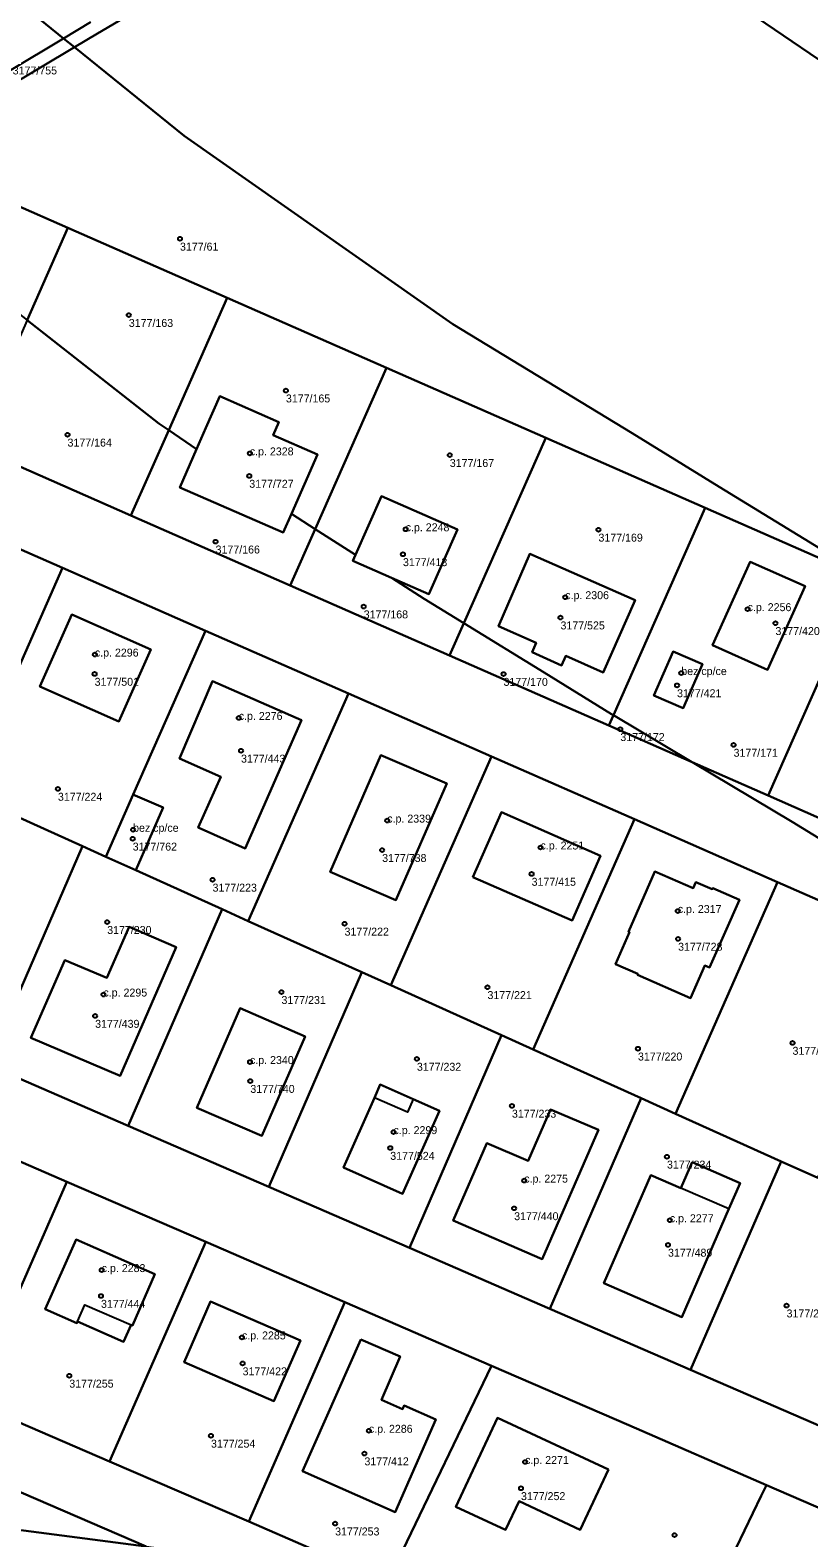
# Model space of a CAD drawing. Extents: x -878211 to -870363, y -1058464 to -1052522.
# Drawn here: x -874243.4 to -874145.4, y -1057039.9 to -1056850 of the extents above; entities that cross this region are included whole.
import ezdxf

# ---------------------------------------------------------------- set-up
doc = ezdxf.new("R2010")
doc.units = 0
for name, color, linetype in [('Definiční body', 7, 'Continuous'), ('Polygon budovy', 7, 'Continuous'), ('Polygon parcely', 7, 'Continuous')]:
    doc.layers.add(name, color=color, linetype=linetype)

msp = doc.modelspace()

# ---------------------------------------------------------------- linework, layer by layer
at = {"layer": 'Definiční body'}
for centre in [(-874224.5, -1056876.24994), (-874230.94, -1056885.85994), (-874211.17, -1056895.36994), (-874238.65, -1056900.92994), (-874215.71, -1056903.27994), (-874190.55, -1056903.49994), (-874215.78, -1056906.11994), (-874196.1, -1056912.83994), (-874171.84, -1056912.89994), (-874220.02, -1056914.39994), (-874196.44, -1056915.98994), (-874176.02, -1056921.38994), (-874201.38, -1056922.56994), (-874153.07, -1056922.89994), (-874176.62, -1056923.95994), (-874149.57, -1056924.66994), (-874235.21, -1056928.61994), (-874235.24, -1056931.05994), (-874183.79, -1056931.06994), (-874161.42, -1056930.94994), (-874161.95, -1056932.49994), (-874217.1, -1056936.59994), (-874169.09, -1056938.01994), (-874216.82, -1056940.73994), (-874154.84, -1056939.99994), (-874239.86, -1056945.53994), (-874198.42, -1056949.52994), (-874230.45, -1056951.81994), (-874230.4, -1056950.68994), (-874199.06, -1056953.24994), (-874179.13, -1056952.91994), (-874220.4, -1056956.98994), (-874180.25, -1056956.24994), (-874161.86, -1056960.91994), (-874233.66, -1056962.31994), (-874203.79, -1056962.52994), (-874161.82, -1056964.42994), (-874211.73, -1056971.13994), (-874185.81, -1056970.51994), (-874234.13, -1056971.43994), (-874235.18, -1056974.13994), (-874166.87, -1056978.25994), (-874147.42, -1056977.53994), (-874215.69, -1056979.93994), (-874194.69, -1056979.54994), (-874215.65, -1056982.33994), (-874182.73, -1056985.45994), (-874197.63, -1056988.76994), (-874198.04, -1056990.76994), (-874163.22, -1056991.86994), (-874181.18, -1056994.87994), (-874182.45, -1056998.36994), (-874162.86, -1056999.86994), (-874163.09, -1057002.96994), (-874234.35, -1057006.14994), (-874234.44, -1057009.40994), (-874148.17, -1057010.61994), (-874216.7, -1057014.62994), (-874216.62, -1057017.90994), (-874238.43, -1057019.45994), (-874220.6, -1057027.01994), (-874200.73, -1057026.38994), (-874201.29, -1057029.24994), (-874181.07, -1057030.31994), (-874181.59, -1057033.62994), (-874204.98, -1057038.07994), (-874162.27, -1057039.52994)]:
    msp.add_circle(centre, 0.25, dxfattribs=at)
at = {"layer": 'Polygon budovy'}
for points in [[(-874210.47, -1056910.89), (-874207.19, -1056903.42), (-874212.78, -1056901), (-874212.05, -1056899.36), (-874219.5, -1056896.09), (-874221.25, -1056900.07), (-874222.42, -1056902.76), (-874224.52, -1056907.56), (-874211.51, -1056913.25)], [(-874202.4, -1056916.07), (-874202.73, -1056916.83), (-874197.89, -1056918.96), (-874193.18, -1056921.03), (-874189.59, -1056912.87), (-874199.13, -1056908.66)], [(-874176.49, -1056929.98), (-874175.96, -1056928.77), (-874171.23, -1056930.86), (-874167.22, -1056921.75), (-874180.46, -1056915.95), (-874184.44, -1056925.03), (-874179.68, -1056927.13), (-874180.2, -1056928.32)], [(-874152.76, -1056916.92), (-874157.49, -1056927.45), (-874150.57, -1056930.55), (-874145.82, -1056919.99)], [(-874228.18, -1056927.97), (-874238.13, -1056923.59), (-874242.13, -1056932.65), (-874232.18, -1056937.03)], [(-874162.45, -1056928.24), (-874164.89, -1056933.76), (-874161.18, -1056935.39), (-874158.74, -1056929.81)], [(-874224.55, -1056941.7), (-874219.38, -1056944.03), (-874222.2, -1056950.41), (-874216.3, -1056953.03), (-874209.22, -1056936.87), (-874220.4, -1056931.97)], [(-874205.6, -1056955.97), (-874197.33, -1056959.57), (-874190.94, -1056944.87), (-874199.21, -1056941.28)], [(-874230.38, -1056946.25), (-874233.82, -1056954.08), (-874230.04, -1056955.79), (-874226.61, -1056947.87), (-874230.14, -1056946.36)], [(-874187.63, -1056956.65), (-874175.14, -1056962.1), (-874171.57, -1056953.95), (-874184.06, -1056948.47)], [(-874167.94, -1056963.59), (-874169.7, -1056967.6), (-874166.88, -1056968.82), (-874166.94, -1056968.96), (-874160.27, -1056971.88), (-874158.45, -1056967.78), (-874157.85, -1056968.04), (-874154.08, -1056959.52), (-874157.46, -1056958.05), (-874157.53, -1056958.18), (-874159.57, -1056957.28), (-874159.92, -1056958.05), (-874164.73, -1056955.94), (-874168.08, -1056963.53)], [(-874243.26, -1056976.9), (-874232.01, -1056981.68), (-874224.97, -1056965.47), (-874230.9, -1056962.91), (-874233.72, -1056969.32), (-874238.98, -1056967.11)], [(-874222.37, -1056985.71), (-874214.19, -1056989.24), (-874208.76, -1056976.71), (-874216.94, -1056973.16)], [(-874200.03, -1056984.43), (-874203.91, -1056993.21), (-874196.5, -1056996.53), (-874191.84, -1056986.1), (-874195.16, -1056984.62), (-874195.89, -1056986.26)], [(-874190.14, -1056999.9), (-874178.91, -1057004.78), (-874171.83, -1056988.47), (-874177.86, -1056985.9), (-874180.69, -1056992.4), (-874185.9, -1056990.16)], [(-874165.25, -1056994.18), (-874171.17, -1057007.81), (-874161.34, -1057012.07), (-874155.42, -1056998.44), (-874161.48, -1056995.81)], [(-874237.56, -1057002.29), (-874241.47, -1057011.07), (-874237.48, -1057012.82), (-874237.4, -1057012.64), (-874236.47, -1057010.53), (-874230.66, -1057013.05), (-874230.48, -1057013.13), (-874227.66, -1057006.66)], [(-874220.68, -1057010.11), (-874223.97, -1057017.73), (-874212.7, -1057022.64), (-874209.33, -1057015.01)], [(-874201.76, -1057014.87), (-874209.09, -1057031.49), (-874197.42, -1057036.64), (-874192.29, -1057024.96), (-874196.31, -1057023.19), (-874196.52, -1057023.66), (-874199.16, -1057022.5), (-874196.78, -1057017.05)], [(-874170.59, -1057031.27), (-874184.53, -1057024.75), (-874189.77, -1057035.97), (-874183.54, -1057038.86), (-874181.82, -1057035.24), (-874174.14, -1057038.85)]]:
    msp.add_lwpolyline(points, close=True, dxfattribs=at)
at = {"layer": 'Polygon parcely'}
for points in [[(-874049.34, -1056914.15), (-874014.23, -1056932.75), (-874007.51, -1056921.23), (-874042.84, -1056899.69), (-874076.67, -1056880.17), (-874135.18, -1056846.79), (-874225.05, -1056794.29), (-874220.11, -1056799.06), (-874203.06, -1056813.57), (-874129.69, -1056863.48), (-874108.33, -1056874.46), (-874102.53, -1056878.64), (-874078.93, -1056895.35), (-874073.45, -1056899.05), (-874056.93, -1056909.47)], [(-874259.1, -1056860.81), (-874259.81, -1056863.37), (-874239.16, -1056851.02), (-874244.49, -1056846.71), (-874246.96, -1056851.65), (-874252.81, -1056857.48)], [(-874239.16, -1056851.02), (-874259.81, -1056863.37), (-874260.34, -1056865.3), (-874260.44, -1056865.68), (-874260.04, -1056865.43), (-874237.79, -1056852.13)], [(-874258.65, -1056866.05), (-874238.61, -1056874.87), (-874218.56, -1056883.68), (-874198.51, -1056892.5), (-874178.47, -1056901.32), (-874158.42, -1056910.14), (-874138.38, -1056918.96), (-874136.75, -1056919.68), (-874156.66, -1056907.49), (-874167.58, -1056900.75), (-874190.16, -1056887.02), (-874223.99, -1056863.27), (-874237.79, -1056852.13), (-874260.04, -1056865.43)], [(-874261.52, -1056872.54), (-874243.74, -1056886.5), (-874238.61, -1056874.87), (-874258.65, -1056866.05)], [(-874225.92, -1056900.36), (-874218.56, -1056883.68), (-874238.61, -1056874.87), (-874243.74, -1056886.5), (-874227.17, -1056899.5)], [(-874212.78, -1056901), (-874207.19, -1056903.42), (-874210.47, -1056910.89), (-874207.48, -1056912.81), (-874198.51, -1056892.5), (-874218.56, -1056883.68), (-874225.92, -1056900.36), (-874222.42, -1056902.76), (-874221.25, -1056900.07), (-874219.5, -1056896.09), (-874212.05, -1056899.36)], [(-874230.67, -1056911.11), (-874225.92, -1056900.36), (-874227.17, -1056899.5), (-874243.74, -1056886.5), (-874250.71, -1056902.29)], [(-874197.89, -1056918.96), (-874193.77, -1056921.6), (-874188.78, -1056924.67), (-874178.47, -1056901.32), (-874198.51, -1056892.5), (-874207.48, -1056912.81), (-874202.4, -1056916.07), (-874199.13, -1056908.66), (-874189.59, -1056912.87), (-874193.18, -1056921.03)], [(-874210.47, -1056910.89), (-874207.19, -1056903.42), (-874212.78, -1056901), (-874212.05, -1056899.36), (-874219.5, -1056896.09), (-874221.25, -1056900.07), (-874222.42, -1056902.76), (-874224.52, -1056907.56), (-874211.51, -1056913.25)], [(-874222.42, -1056902.76), (-874225.92, -1056900.36), (-874230.67, -1056911.11), (-874210.62, -1056919.93), (-874207.48, -1056912.81), (-874210.47, -1056910.89), (-874211.51, -1056913.25), (-874224.52, -1056907.56)], [(-874158.42, -1056910.14), (-874178.47, -1056901.32), (-874188.78, -1056924.67), (-874178.68, -1056930.87), (-874170.2, -1056936.13), (-874169.96, -1056936.27)], [(-874254.36, -1056944.8), (-874251.74, -1056945.99), (-874239.29, -1056917.7), (-874257.28, -1056909.78), (-874269.65, -1056937.89)], [(-874197.89, -1056918.96), (-874193.18, -1056921.03), (-874189.59, -1056912.87), (-874199.13, -1056908.66), (-874202.4, -1056916.07), (-874202.73, -1056916.83)], [(-874160.03, -1056942.19), (-874150.49, -1056946.39), (-874138.38, -1056918.96), (-874158.42, -1056910.14), (-874169.96, -1056936.27)], [(-874202.73, -1056916.83), (-874202.4, -1056916.07), (-874207.48, -1056912.81), (-874210.62, -1056919.93), (-874190.58, -1056928.75), (-874188.78, -1056924.67), (-874193.77, -1056921.6), (-874197.89, -1056918.96)], [(-874233.82, -1056954.08), (-874230.38, -1056946.25), (-874221.3, -1056925.63), (-874239.29, -1056917.7), (-874251.74, -1056945.99), (-874236.77, -1056952.75)], [(-874184.44, -1056925.03), (-874179.68, -1056927.13), (-874180.2, -1056928.32), (-874176.49, -1056929.98), (-874175.96, -1056928.77), (-874171.23, -1056930.86), (-874167.22, -1056921.75), (-874180.46, -1056915.95)], [(-874184.44, -1056925.03), (-874180.46, -1056915.95), (-874167.22, -1056921.75), (-874171.23, -1056930.86), (-874175.96, -1056928.77), (-874176.49, -1056929.98), (-874180.2, -1056928.32), (-874179.68, -1056927.13)], [(-874157.49, -1056927.45), (-874152.76, -1056916.92), (-874145.82, -1056919.99), (-874150.57, -1056930.55)], [(-874157.49, -1056927.45), (-874150.57, -1056930.55), (-874145.82, -1056919.99), (-874152.76, -1056916.92)], [(-874119.6, -1056930.66), (-874118.33, -1056927.78), (-874136.75, -1056919.68), (-874138.38, -1056918.96), (-874150.49, -1056946.39), (-874130.44, -1056955.21)], [(-874232.18, -1056937.03), (-874228.18, -1056927.97), (-874238.13, -1056923.59), (-874242.13, -1056932.65)], [(-874232.18, -1056937.03), (-874242.13, -1056932.65), (-874238.13, -1056923.59), (-874228.18, -1056927.97)], [(-874170.53, -1056937.57), (-874169.96, -1056936.27), (-874170.2, -1056936.13), (-874178.68, -1056930.87), (-874188.78, -1056924.67), (-874190.58, -1056928.75)], [(-874230.38, -1056946.25), (-874230.14, -1056946.36), (-874226.61, -1056947.87), (-874230.04, -1056955.79), (-874219.19, -1056960.69), (-874215.9, -1056962.18), (-874203.3, -1056933.53), (-874221.3, -1056925.63)], [(-874158.74, -1056929.81), (-874161.18, -1056935.39), (-874164.89, -1056933.76), (-874162.45, -1056928.24)], [(-874158.74, -1056929.81), (-874162.45, -1056928.24), (-874164.89, -1056933.76), (-874161.18, -1056935.39)], [(-874216.3, -1056953.03), (-874222.2, -1056950.41), (-874219.38, -1056944.03), (-874224.55, -1056941.7), (-874220.4, -1056931.97), (-874209.22, -1056936.87)], [(-874216.3, -1056953.03), (-874209.22, -1056936.87), (-874220.4, -1056931.97), (-874224.55, -1056941.7), (-874219.38, -1056944.03), (-874222.2, -1056950.41)], [(-874215.9, -1056962.18), (-874201.61, -1056968.63), (-874197.98, -1056970.27), (-874185.3, -1056941.45), (-874203.3, -1056933.53)], [(-874170.53, -1056937.57), (-874160.03, -1056942.19), (-874169.96, -1056936.27)], [(-874190.94, -1056944.87), (-874197.33, -1056959.57), (-874205.6, -1056955.97), (-874199.21, -1056941.28)], [(-874190.94, -1056944.87), (-874199.21, -1056941.28), (-874205.6, -1056955.97), (-874197.33, -1056959.57)], [(-874184.03, -1056976.57), (-874180.07, -1056978.36), (-874167.31, -1056949.37), (-874185.3, -1056941.45), (-874197.98, -1056970.27)], [(-874254.36, -1056944.8), (-874266.42, -1056972.63), (-874248.73, -1056980.31), (-874236.77, -1056952.75), (-874251.74, -1056945.99)], [(-874233.82, -1056954.08), (-874230.04, -1056955.79), (-874226.61, -1056947.87), (-874230.14, -1056946.36), (-874230.38, -1056946.25)], [(-874187.63, -1056956.65), (-874184.06, -1056948.47), (-874171.57, -1056953.95), (-874175.14, -1056962.1)], [(-874187.63, -1056956.65), (-874175.14, -1056962.1), (-874171.57, -1056953.95), (-874184.06, -1056948.47)], [(-874149.31, -1056957.28), (-874167.31, -1056949.37), (-874180.07, -1056978.36), (-874166.45, -1056984.51), (-874162.15, -1056986.46)], [(-874230.04, -1056955.79), (-874233.82, -1056954.08), (-874236.77, -1056952.75), (-874248.73, -1056980.31), (-874231.03, -1056987.99), (-874219.19, -1056960.69)], [(-874159.57, -1056957.28), (-874159.92, -1056958.05), (-874164.73, -1056955.94), (-874168.08, -1056963.53), (-874167.94, -1056963.59), (-874169.7, -1056967.6), (-874166.88, -1056968.82), (-874166.94, -1056968.96), (-874160.27, -1056971.88), (-874158.45, -1056967.78), (-874157.85, -1056968.04), (-874154.08, -1056959.52), (-874157.46, -1056958.05), (-874157.53, -1056958.18)], [(-874159.57, -1056957.28), (-874157.53, -1056958.18), (-874157.46, -1056958.05), (-874154.08, -1056959.52), (-874157.85, -1056968.04), (-874158.45, -1056967.78), (-874160.27, -1056971.88), (-874166.94, -1056968.96), (-874166.88, -1056968.82), (-874169.7, -1056967.6), (-874167.94, -1056963.59), (-874168.08, -1056963.53), (-874164.73, -1056955.94), (-874159.92, -1056958.05)], [(-874162.15, -1056986.46), (-874148.87, -1056992.46), (-874144.22, -1056994.54), (-874131.32, -1056965.2), (-874149.31, -1056957.28)], [(-874231.03, -1056987.99), (-874213.34, -1056995.67), (-874201.61, -1056968.63), (-874215.9, -1056962.18), (-874219.19, -1056960.69)], [(-874238.98, -1056967.11), (-874243.26, -1056976.9), (-874232.01, -1056981.68), (-874224.97, -1056965.47), (-874230.9, -1056962.91), (-874233.72, -1056969.32)], [(-874238.98, -1056967.11), (-874233.72, -1056969.32), (-874230.9, -1056962.91), (-874224.97, -1056965.47), (-874232.01, -1056981.68), (-874243.26, -1056976.9)], [(-874201.61, -1056968.63), (-874213.34, -1056995.67), (-874195.64, -1057003.35), (-874184.03, -1056976.57), (-874197.98, -1056970.27)], [(-874214.19, -1056989.24), (-874208.76, -1056976.71), (-874216.94, -1056973.16), (-874222.37, -1056985.71)], [(-874214.19, -1056989.24), (-874222.37, -1056985.71), (-874216.94, -1056973.16), (-874208.76, -1056976.71)], [(-874184.03, -1056976.57), (-874195.64, -1057003.35), (-874177.95, -1057011.03), (-874166.45, -1056984.51), (-874180.07, -1056978.36)], [(-874191.84, -1056986.1), (-874195.16, -1056984.62), (-874199.3, -1056982.78), (-874200.03, -1056984.43), (-874203.91, -1056993.21), (-874196.5, -1056996.53)], [(-874191.84, -1056986.1), (-874196.5, -1056996.53), (-874203.91, -1056993.21), (-874200.03, -1056984.43), (-874199.3, -1056982.78), (-874195.16, -1056984.62)], [(-874180.69, -1056992.4), (-874177.86, -1056985.9), (-874171.83, -1056988.47), (-874178.91, -1057004.78), (-874190.14, -1056999.9), (-874185.9, -1056990.16)], [(-874180.69, -1056992.4), (-874185.9, -1056990.16), (-874190.14, -1056999.9), (-874178.91, -1057004.78), (-874171.83, -1056988.47), (-874177.86, -1056985.9)], [(-874166.45, -1056984.51), (-874177.95, -1057011.03), (-874160.25, -1057018.71), (-874148.87, -1056992.46), (-874162.15, -1056986.46)], [(-874268.34, -1057015.15), (-874250.85, -1057022.71), (-874238.72, -1056995.01), (-874256.21, -1056987.42)], [(-874323.63, -1056990.47), (-874327.17, -1056998.46), (-874318.73, -1057002.1), (-874286.59, -1057015.98), (-874258.4, -1057028.16), (-874228.74, -1057040.96), (-874199.95, -1057044.7), (-874208.32, -1057041.08), (-874215.85, -1057037.83), (-874233.35, -1057030.27), (-874250.85, -1057022.71), (-874268.34, -1057015.15), (-874285.84, -1057007.59), (-874303.34, -1057000.03), (-874316.81, -1056994.21)], [(-874160.05, -1056992.56), (-874161.48, -1056995.81), (-874165.25, -1056994.18), (-874171.17, -1057007.81), (-874161.34, -1057012.07), (-874155.42, -1056998.44), (-874154.02, -1056995.18)], [(-874160.05, -1056992.56), (-874154.02, -1056995.18), (-874155.42, -1056998.44), (-874161.34, -1057012.07), (-874171.17, -1057007.81), (-874165.25, -1056994.18), (-874161.48, -1056995.81)], [(-874142.56, -1057026.39), (-874131.25, -1057000.32), (-874144.22, -1056994.54), (-874148.87, -1056992.46), (-874160.25, -1057018.71)], [(-874233.35, -1057030.27), (-874221.24, -1057002.6), (-874238.72, -1056995.01), (-874250.85, -1057022.71)], [(-874227.66, -1057006.66), (-874230.48, -1057013.13), (-874230.66, -1057013.05), (-874231.62, -1057015.17), (-874237.4, -1057012.64), (-874237.48, -1057012.82), (-874241.47, -1057011.07), (-874237.56, -1057002.29)], [(-874227.66, -1057006.66), (-874237.56, -1057002.29), (-874241.47, -1057011.07), (-874237.48, -1057012.82), (-874237.4, -1057012.64), (-874231.62, -1057015.17), (-874230.66, -1057013.05), (-874230.48, -1057013.13)], [(-874203.75, -1057010.19), (-874221.24, -1057002.6), (-874233.35, -1057030.27), (-874215.85, -1057037.83)], [(-874223.97, -1057017.73), (-874220.68, -1057010.11), (-874209.33, -1057015.01), (-874212.7, -1057022.64)], [(-874223.97, -1057017.73), (-874212.7, -1057022.64), (-874209.33, -1057015.01), (-874220.68, -1057010.11)], [(-874197.01, -1057042.56), (-874185.32, -1057018.19), (-874203.75, -1057010.19), (-874215.85, -1057037.83), (-874208.32, -1057041.08)], [(-874201.76, -1057014.87), (-874196.78, -1057017.05), (-874199.16, -1057022.5), (-874196.52, -1057023.66), (-874196.31, -1057023.19), (-874192.29, -1057024.96), (-874197.42, -1057036.64), (-874209.09, -1057031.49)], [(-874201.76, -1057014.87), (-874209.09, -1057031.49), (-874197.42, -1057036.64), (-874192.29, -1057024.96), (-874196.31, -1057023.19), (-874196.52, -1057023.66), (-874199.16, -1057022.5), (-874196.78, -1057017.05)], [(-874177.32, -1057045.1), (-874157.64, -1057047.67), (-874151.36, -1057034.58), (-874150.7, -1057033.22), (-874168.01, -1057025.7), (-874185.32, -1057018.19), (-874197.01, -1057042.56)], [(-874170.59, -1057031.27), (-874174.14, -1057038.85), (-874181.82, -1057035.24), (-874183.54, -1057038.86), (-874189.77, -1057035.97), (-874184.53, -1057024.75)], [(-874170.59, -1057031.27), (-874184.53, -1057024.75), (-874189.77, -1057035.97), (-874183.54, -1057038.86), (-874181.82, -1057035.24), (-874174.14, -1057038.85)], [(-874228.74, -1057040.96), (-874258.4, -1057028.16), (-874261.85, -1057036.65), (-874258.41, -1057037.1), (-874254.31, -1057037.63), (-874249.05, -1057038.32)], [(-874148.96, -1057051.32), (-874137.71, -1057052.78), (-874132.36, -1057041.19), (-874150.7, -1057033.22), (-874151.36, -1057034.58), (-874157.64, -1057047.67), (-874158.78, -1057050.04)], [(-874264.68, -1057043.63), (-874238.04, -1057054.77), (-874235.3, -1057056.13), (-874228.74, -1057040.96), (-874249.05, -1057038.32), (-874254.31, -1057037.63), (-874258.41, -1057037.1), (-874261.85, -1057036.65)]]:
    msp.add_lwpolyline(points, close=True, dxfattribs=at)
for points in [[(-874129.69, -1056863.48), (-874203.06, -1056813.57)], [(-874244.49, -1056846.71), (-874239.16, -1056851.02), (-874235.74, -1056848.97)], [(-874235.74, -1056848.97), (-874239.16, -1056851.02), (-874237.79, -1056852.13), (-874234.9, -1056850.4), (-874227.26, -1056845.87)], [(-874227.26, -1056845.87), (-874234.9, -1056850.4), (-874237.79, -1056852.13), (-874223.99, -1056863.27), (-874190.16, -1056887.02), (-874167.58, -1056900.75), (-874156.66, -1056907.49), (-874136.75, -1056919.68)], [(-874142.56, -1057026.39), (-874160.25, -1057018.71), (-874177.95, -1057011.03), (-874195.64, -1057003.35), (-874213.34, -1056995.67), (-874231.03, -1056987.99), (-874248.73, -1056980.31), (-874266.42, -1056972.63), (-874284.12, -1056964.95), (-874301.81, -1056957.27), (-874292.24, -1056927.69), (-874287.47, -1056913.16), (-874275.44, -1056901.79), (-874257.28, -1056909.78), (-874239.29, -1056917.7), (-874221.3, -1056925.63), (-874203.3, -1056933.53), (-874185.3, -1056941.45), (-874167.31, -1056949.37), (-874149.31, -1056957.28), (-874131.32, -1056965.2)], [(-874147.48, -1056949.67), (-874160.03, -1056942.19), (-874170.53, -1056937.57), (-874190.58, -1056928.75), (-874210.62, -1056919.93), (-874230.67, -1056911.11), (-874250.71, -1056902.29)], [(-874130.44, -1056955.21), (-874150.49, -1056946.39), (-874160.03, -1056942.19), (-874147.48, -1056949.67), (-874127.97, -1056961.66)], [(-874127.97, -1056961.66), (-874147.48, -1056949.67)], [(-874311.71, -1056963.32), (-874307.45, -1056965.17), (-874291.17, -1056972.24), (-874273.69, -1056979.83), (-874256.21, -1056987.42), (-874238.72, -1056995.01), (-874221.24, -1057002.6), (-874203.75, -1057010.19), (-874185.32, -1057018.19), (-874168.01, -1057025.7), (-874150.7, -1057033.22), (-874132.36, -1057041.19)]]:
    msp.add_lwpolyline(points, dxfattribs=at)

# ---------------------------------------------------------------- texts
at = {"layer": 'Definiční body'}
for s, p in [('3177/755', (-874245.55, -1056855.549)), ('3177/61', (-874224.5, -1056877.739)), ('3177/163', (-874230.94, -1056887.349)), ('3177/165', (-874211.17, -1056896.859)), ('3177/164', (-874238.65, -1056902.419)), ('c.p. 2328', (-874215.71, -1056903.53)), ('3177/167', (-874190.55, -1056904.989)), ('3177/727', (-874215.78, -1056907.609)), ('c.p. 2248', (-874196.1, -1056913.09)), ('3177/169', (-874171.84, -1056914.389)), ('3177/166', (-874220.02, -1056915.889)), ('3177/413', (-874196.44, -1056917.479)), ('c.p. 2306', (-874176.02, -1056921.639)), ('3177/168', (-874201.38, -1056924.059)), ('c.p. 2256', (-874153.07, -1056923.149)), ('3177/525', (-874176.62, -1056925.449)), ('3177/420', (-874149.57, -1056926.159)), ('c.p. 2296', (-874235.21, -1056928.87)), ('bez cp/ce', (-874161.42, -1056931.2)), ('3177/501', (-874235.24, -1056932.549)), ('3177/170', (-874183.79, -1056932.559)), ('3177/421', (-874161.95, -1056933.989)), ('c.p. 2276', (-874217.1, -1056936.85)), ('3177/172', (-874169.09, -1056939.509)), ('3177/171', (-874154.84, -1056941.489)), ('3177/443', (-874216.82, -1056942.229)), ('3177/224', (-874239.86, -1056947.029)), ('bez cp/ce', (-874230.4, -1056950.94)), ('c.p. 2339', (-874198.42, -1056949.78)), ('3177/762', (-874230.45, -1056953.309)), ('3177/738', (-874199.06, -1056954.739)), ('c.p. 2251', (-874179.13, -1056953.169)), ('3177/223', (-874220.4, -1056958.479)), ('3177/415', (-874180.25, -1056957.739)), ('c.p. 2317', (-874161.86, -1056961.169)), ('3177/230', (-874233.66, -1056963.809)), ('3177/222', (-874203.79, -1056964.019)), ('3177/728', (-874161.82, -1056965.919)), ('c.p. 2295', (-874234.13, -1056971.69)), ('3177/221', (-874185.81, -1056972.009)), ('3177/231', (-874211.73, -1056972.629)), ('3177/439', (-874235.18, -1056975.629)), ('3177/219', (-874147.42, -1056979.029)), ('c.p. 2340', (-874215.69, -1056980.19)), ('3177/232', (-874194.69, -1056981.039)), ('3177/220', (-874166.87, -1056979.749)), ('3177/740', (-874215.65, -1056983.829)), ('3177/233', (-874182.73, -1056986.949)), ('c.p. 2299', (-874197.63, -1056989.02)), ('3177/524', (-874198.04, -1056992.259)), ('3177/234', (-874163.22, -1056993.359)), ('c.p. 2275', (-874181.18, -1056995.129)), ('3177/440', (-874182.45, -1056999.859)), ('c.p. 2277', (-874162.86, -1057000.12)), ('3177/489', (-874163.09, -1057004.459)), ('c.p. 2283', (-874234.35, -1057006.399)), ('3177/444', (-874234.44, -1057010.899)), ('3177/235', (-874148.17, -1057012.109)), ('c.p. 2285', (-874216.7, -1057014.879)), ('3177/422', (-874216.62, -1057019.399)), ('3177/255', (-874238.43, -1057020.949)), ('c.p. 2286', (-874200.73, -1057026.639)), ('3177/254', (-874220.6, -1057028.509)), ('3177/412', (-874201.29, -1057030.739)), ('c.p. 2271', (-874181.07, -1057030.57)), ('3177/252', (-874181.59, -1057035.119)), ('3177/253', (-874204.98, -1057039.569))]:
    msp.add_text(s, height=0.999996, dxfattribs=at).set_placement(p)

doc.saveas('drawing.dxf')
